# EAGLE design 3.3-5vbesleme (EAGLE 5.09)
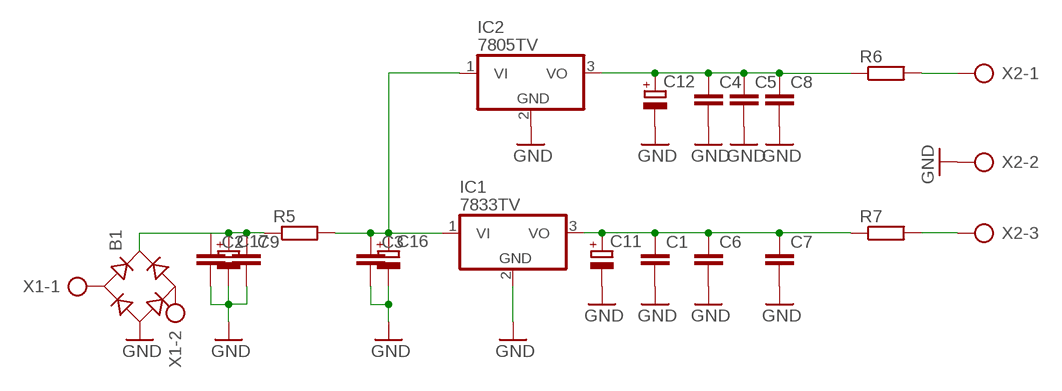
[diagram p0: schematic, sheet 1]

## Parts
B1  RB1A  [RB1A]
C1  C5/2.5  [C5B2.5]
C2  C5/2.5  [C5B2.5]
C3  C5/2.5  [C5B2.5]
C4  C5/2.5  [C5B2.5]
C5  C5/2.5  [C5B2.5]
C6  C5/2.5  [C5B2.5]
C7  C5/2.5  [C5B2.5]
C8  C5/2.5  [C5B2.5]
C9  C5/2.5  [C5B2.5]
C11  CPOL-EUE5-6  [E5-6]
C12  CPOL-EUE5-6  [E5-6]
C16  CPOL-EUE5-10.5  [E5-10,5]
C17  CPOL-EUE5-10.5  [E5-10,5]
IC1  7833TV  7805TV  [TO220V]
IC2  7805TV  [TO220V]
R5  R-EU_0411/15  [0411/15]
R6  R-EU_0207/12  [0207/12]
R7  R-EU_0207/12  [0207/12]
X1  AK300/2  [AK300/2]
X2  AK300/3  [AK300/3]

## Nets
GND: B1.- C1.2 C2.2 C3.2 C4.2 C5.2 C6.2 C7.2 C8.2 C9.2 C11.- C12.- C16.- C17.- IC1.2(GND) IC2.2(GND) X2.2
N$1: B1.+ C2.1 C9.1 C17.+ R5.1
N$2: C3.1 C16.+ IC1.1(VI) IC2.1(VI) R5.2
N$3: R7.2 X2.3
N$4: R6.2 X2.1
N$5: C4.1 C5.1 C8.1 C12.+ IC2.3(VO) R6.1
N$6: C1.1 C6.1 C7.1 C11.+ IC1.3(VO) R7.1
N$12: B1.AC1 X1.1
N$13: B1.AC2 X1.2

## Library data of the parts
B1 = rectifier:RB1A: RECTIFIER 1 A
C1-C9 = capacitor-wima:C: CAPACITOR
C11 C12 = rcl:CPOL-EU: POLARIZED CAPACITOR, European symbol
C16 C17 = resistor:CPOL-EU: POLARIZED CAPACITOR, European symbol
IC1 IC2 = linear:78*: Positive VOLTAGE REGULATOR Source: http://cache.national.com/ds/LM/LM78L05.pdf http://www.fairchildsemi.com/ds/LM/LM7805.pdf
R5-R7 = resistor:R-EU_: RESISTOR, European symbol
X1 = con-ptr500:AK300/2: CONNECTOR
X2 = con-ptr500:AK300/3: CONNECTOR

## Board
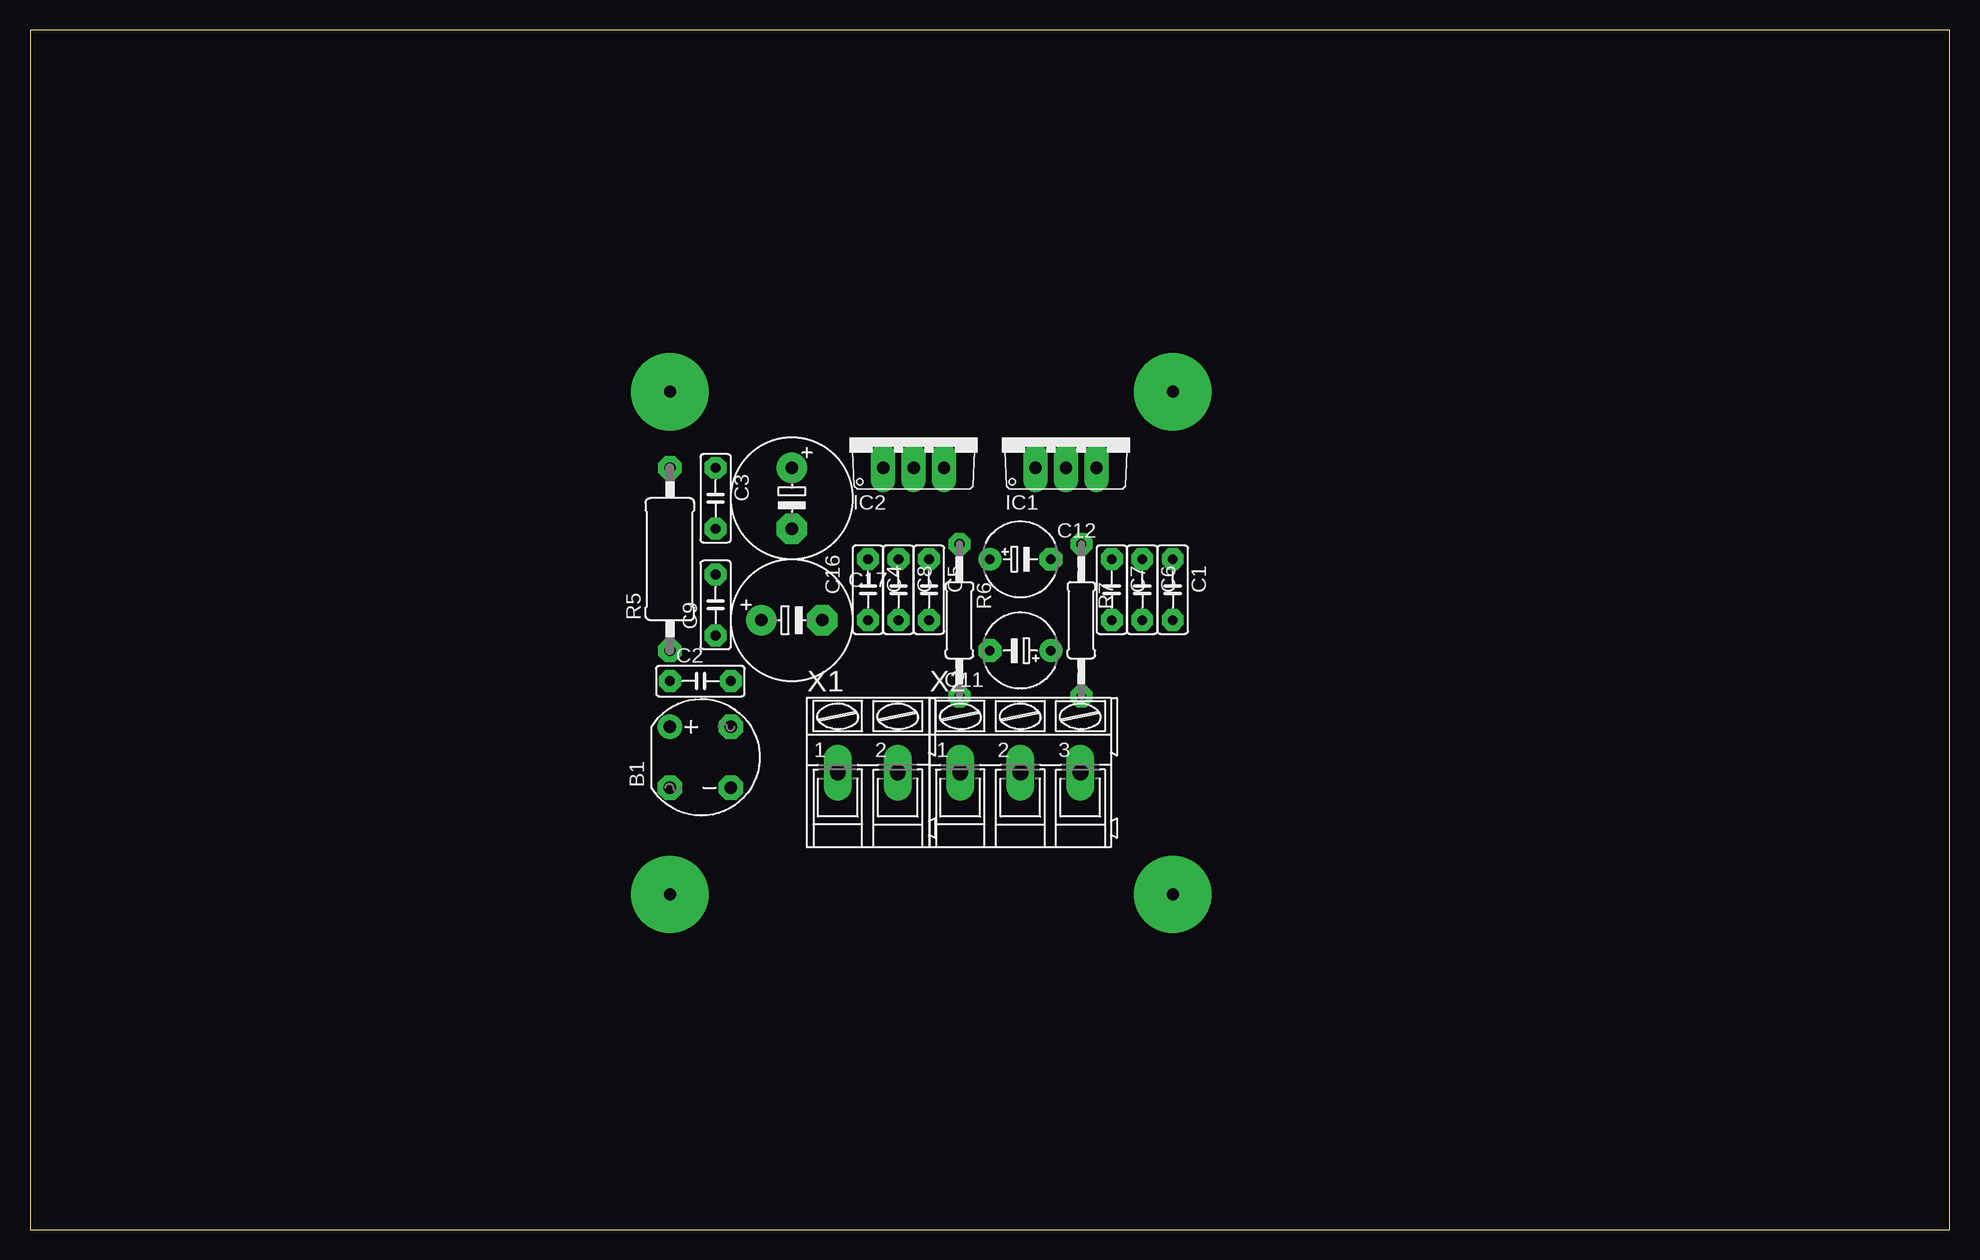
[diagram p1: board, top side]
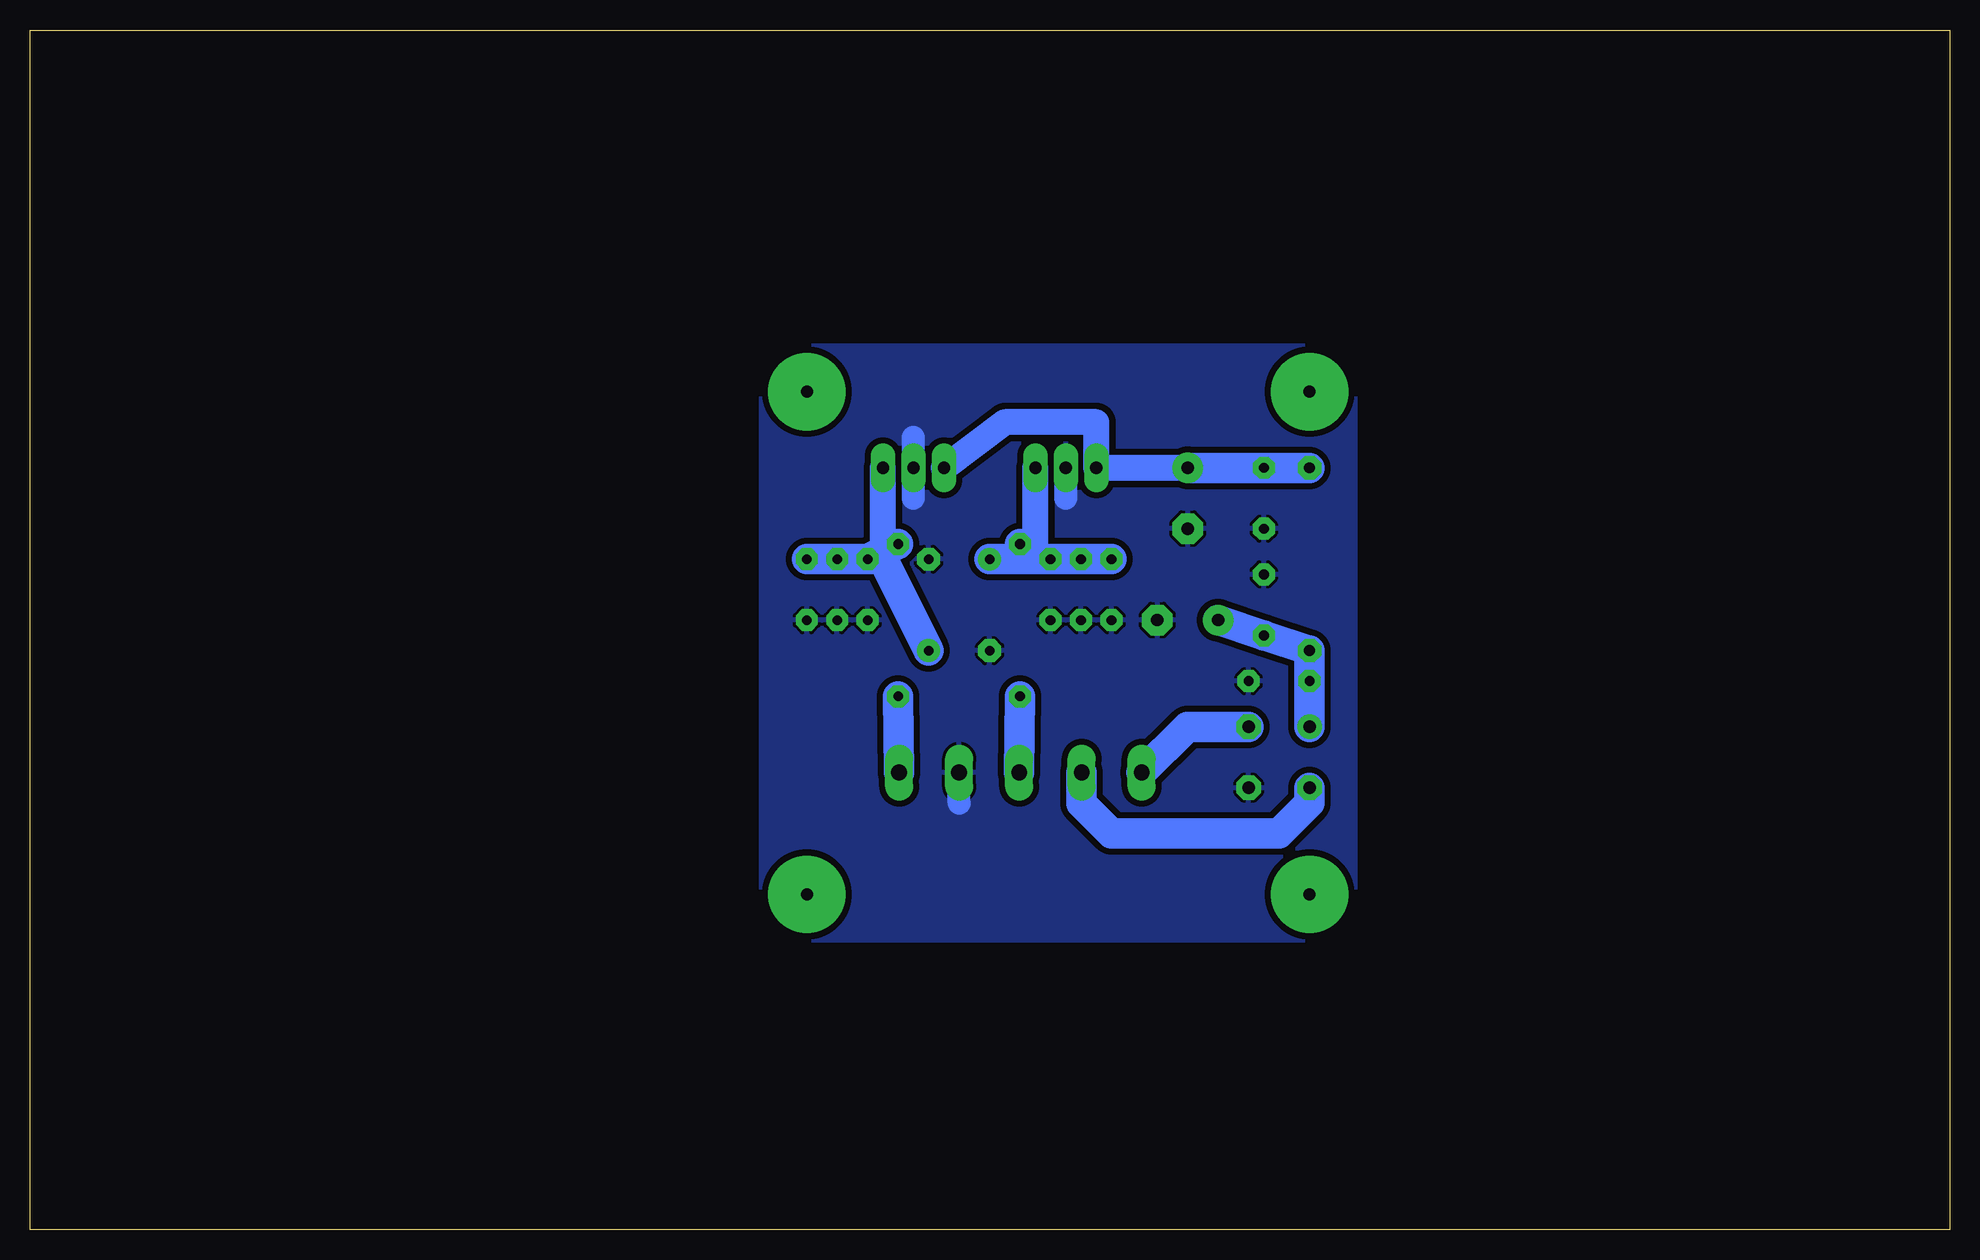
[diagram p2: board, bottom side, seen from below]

Size 160 x 100 mm. Coordinates in mm from the lower left corner, seen from the top.
Outline: 0,0 160,0 160,100 0,100 0,0
Copper layers (1*16): Top 0.035mm / dielectric 1.5mm / Bottom 0.035mm
Design rules "default *": minimum track width 10mil, minimum drill 24mil, track to track 20mil, track to pad 20mil, pad to pad 20mil, via to via 20mil, smd to smd 8mil, copper to edge 40mil, drill to drill 8mil, minimum pad ring 20mil, minimum via ring 20mil, stop-mask expansion 4mil, vias tented up to drill 0mil, thermal gap 10mil

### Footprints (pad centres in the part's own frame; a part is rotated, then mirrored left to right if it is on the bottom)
RB1A = drill 1.016 round: + -2.54,2.54 | drill 1.016 octagon: - 2.54,-2.54; AC1 2.54,2.54; AC2 -2.54,-2.54
C5B2.5 = drill 0.813 pad 1.6 octagon: 1 -2.54,0; 2 2.54,0
E5-6 = drill 0.813 pad 1.905 round: + -2.54,0 | drill 0.813 pad 1.905 octagon: - 2.54,0
E5-10,5 = drill 1.016 pad 2.54 round: + -2.54,0 | drill 1.016 pad 2.54 octagon: - 2.54,0
TO220V = drill 1.016 long: 1 -2.54,-2.54; 2 0,-2.54; 3 2.54,-2.54
0411/15 = drill 0.914 octagon: 1 -7.62,0; 2 7.62,0
0207/12 = drill 0.813 octagon: 1 -6.35,0; 2 6.35,0
AK300/2 = drill 1.321 long: 1 -2.515,0; 2 2.489,0
AK300/3 = drill 1.321 long: 1 -5.004,0; 2 0,0; 3 5.004,0

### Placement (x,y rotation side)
B1  55.88,39.37 0 top
C1  95.25,53.34 270 top
C2  55.88,45.72 0 top
C3  57.15,60.96 270 top
C4  69.85,53.34 270 top
C5  74.93,53.34 270 top
C6  92.71,53.34 270 top
C7  90.17,53.34 270 top
C8  72.39,53.34 270 top
C9  57.15,52.07 90 top
C11  82.55,48.26 180 top
C12  82.55,55.88 0 top
C16  63.5,60.96 270 top
C17  63.5,50.8 0 top
IC1  86.36,66.04 0 top
IC2  73.66,66.04 0 top
R5  53.34,55.88 90 top
R6  77.47,50.8 270 top
R7  87.63,50.8 270 top
X1  69.85,38.1 0 top
X2  82.55,38.1 0 top

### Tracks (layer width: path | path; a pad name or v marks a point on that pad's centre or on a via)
GND
  Bottom 1.93: 86.36,60.96 IC1.2 86.36,66.04 | 73.66,60.96 IC2.2 | 82.55,35.56 X2.2
  pour Bottom: 49.53,73.66 99.06,73.66 99.06,24.13 49.53,24.13
N$1
  Bottom 2.54: C17.+ C9.1 R5.1 C2.1 B1.+
N$2
  Bottom 2.184: IC1.1 78.74,67.31 71.12,67.31 IC2.1 C16.+
  Bottom 2.54: R5.2 C3.1 C16.+
N$3
  Bottom 2.54: X2.3 R7.2
N$4
  Bottom 2.54: X2.1 R6.2
N$5
  Bottom 1.27: C5.1 76.2,55.88
  Bottom 2.184: 76.2,55.88 IC2.3
  Bottom 2.54: C4.1 C8.1 C5.1 C12.+ | 76.2,55.88 R6.1
N$6
  Bottom 1.27: C7.1 88.9,57.15
  Bottom 2.184: 88.9,57.15 IC1.3
  Bottom 2.54: C11.+ 88.9,55.88 C7.1 | C7.1 C6.1 C1.1 | C7.1 R7.1
N$7  (via drill 1 pad 6.45)
  other vias: 53.34,69.85
N$8  (via drill 1 pad 6.45)
  other vias: 95.25,69.85
N$9  (via drill 1 pad 6.45)
  other vias: 95.25,27.94
N$10  (via drill 1 pad 6.45)
  other vias: 53.34,27.94
N$12
  Bottom 2.54: B1.AC1 63.52,41.91 X1.1
N$13
  Bottom 2.54: B1.AC2 53.34,35.56 55.88,33.02 69.85,33.02 72.34,35.51 X1.2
